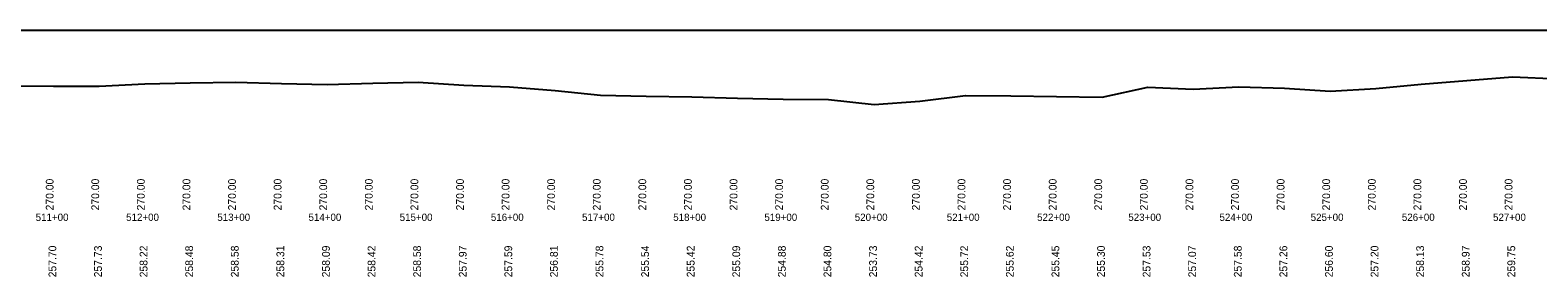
# Model space of a CAD drawing. Extents: x 1354 to 11940, y 17935 to 18885.
# Drawn here: x 5014 to 6668, y 17938 to 18209 of the extents above; entities that cross this region are included whole.
import ezdxf

# ---------------------------------------------------------------- set-up
doc = ezdxf.new("R2010")
doc.units = 0
for name, color, linetype in [('Level 40', 7, 'Continuous'), ('Level 42', 7, 'Continuous'), ('Level 43', 7, 'Continuous'), ('Level 45', 7, 'Continuous')]:
    doc.layers.add(name, color=color, linetype=linetype)

msp = doc.modelspace()

# ---------------------------------------------------------------- linework, layer by layer
at = {"layer": 'Level 40'}
for points in [[(6439.7, 18141.5), (6489.7, 18144.5), (6539.7, 18149.2), (6589.7, 18153.3), (6639.7, 18157.3), (6689.7, 18155.2)], [(4989.7, 18147.5), (5039.7, 18147), (5089.7, 18147.1), (5139.7, 18149.6), (5189.7, 18150.9), (5239.7, 18151.4), (5289.7, 18150), (5339.7, 18149), (5389.7, 18150.6), (5439.7, 18151.4), (5489.7, 18148.4), (5539.7, 18146.5), (5589.7, 18142.5), (5639.7, 18137.4), (5689.7, 18136.2), (5739.7, 18135.6), (5789.7, 18133.9), (5839.7, 18132.9), (5889.7, 18132.5), (5939.7, 18127.1), (5989.7, 18130.6), (6039.7, 18137.1), (6089.7, 18136.6), (6139.7, 18135.7), (6189.7, 18135), (6239.7, 18146.1), (6289.7, 18143.9), (6339.7, 18146.4), (6389.7, 18144.8), (6439.7, 18141.5)]]:
    msp.add_lwpolyline(points, dxfattribs=at)
at = {"layer": 'Level 45'}
msp.add_line((4474.7, 18208.5), (8339.7, 18208.5), dxfattribs=at)

# ---------------------------------------------------------------- texts
at = {"layer": 'Level 42'}
for s, p in [('511+00', (5020.1, 17999.5)), ('512+00', (5119.3, 17999.5)), ('513+00', (5219.3, 17999.5)), ('514+00', (5319.3, 17999.5)), ('515+00', (5419.3, 17999.5)), ('516+00', (5519.3, 17999.5)), ('517+00', (5619.3, 17999.5)), ('518+00', (5719.3, 17999.5)), ('519+00', (5819.3, 17999.5)), ('520+00', (5918.4, 17999.5)), ('521+00', (6019.3, 17999.5)), ('522+00', (6118.4, 17999.5)), ('523+00', (6218.4, 17999.5)), ('524+00', (6318.4, 17999.5)), ('525+00', (6418.4, 17999.5)), ('526+00', (6518.4, 17999.5)), ('527+00', (6618.4, 17999.5))]:
    msp.add_text(s, height=8, dxfattribs=at).set_placement(p)
at = {"layer": 'Level 43'}
for s, p in [('270.00', (5039.7, 18011)), ('270.00', (5089.7, 18011)), ('270.00', (5139.7, 18011)), ('270.00', (5189.7, 18011)), ('270.00', (5239.7, 18011)), ('270.00', (5289.7, 18011)), ('270.00', (5339.7, 18011)), ('270.00', (5389.7, 18011)), ('270.00', (5439.7, 18011)), ('270.00', (5489.7, 18011)), ('270.00', (5539.7, 18011)), ('270.00', (5589.7, 18011)), ('270.00', (5639.7, 18011)), ('270.00', (5689.7, 18011)), ('270.00', (5739.7, 18011)), ('270.00', (5789.7, 18011)), ('270.00', (5839.7, 18011)), ('270.00', (5889.7, 18011)), ('270.00', (5939.7, 18011)), ('270.00', (5989.7, 18011)), ('270.00', (6039.7, 18011)), ('270.00', (6089.7, 18011)), ('270.00', (6139.7, 18011)), ('270.00', (6189.7, 18011)), ('270.00', (6239.7, 18011)), ('270.00', (6289.7, 18011)), ('270.00', (6339.7, 18011)), ('270.00', (6389.7, 18011)), ('270.00', (6439.7, 18011)), ('270.00', (6489.7, 18011)), ('270.00', (6539.7, 18011)), ('270.00', (6589.7, 18011)), ('270.00', (6639.7, 18011)), ('257.70', (5042.7, 17937.7)), ('257.73', (5092.7, 17937.7)), ('258.22', (5142.7, 17937.7)), ('258.48', (5192.7, 17937.7)), ('258.58', (5242.7, 17937.7)), ('258.31', (5292.7, 17937.7)), ('258.09', (5342.7, 17937.7)), ('258.42', (5392.7, 17937.7)), ('258.58', (5442.7, 17937.7)), ('257.97', (5492.7, 17937.7)), ('257.59', (5542.7, 17937.7)), ('256.81', (5592.7, 17937.7)), ('255.78', (5642.7, 17937.7)), ('255.54', (5692.7, 17937.7)), ('255.42', (5742.7, 17937.7)), ('255.09', (5792.7, 17937.7)), ('254.88', (5842.7, 17937.7)), ('254.80', (5892.7, 17937.7)), ('253.73', (5942.7, 17937.7)), ('254.42', (5992.7, 17937.7)), ('255.72', (6042.7, 17937.7)), ('255.62', (6092.7, 17937.7)), ('255.45', (6142.7, 17937.7)), ('255.30', (6192.7, 17937.7)), ('257.53', (6242.7, 17937.7)), ('257.07', (6292.7, 17937.7)), ('257.58', (6342.7, 17937.7)), ('257.26', (6392.7, 17937.7)), ('256.60', (6442.7, 17937.7)), ('257.20', (6492.7, 17937.7)), ('258.13', (6542.7, 17937.7)), ('258.97', (6592.7, 17937.7)), ('259.75', (6642.7, 17937.7))]:
    msp.add_text(s, height=8.5, rotation=90, dxfattribs=at).set_placement(p)

doc.saveas('drawing.dxf')
